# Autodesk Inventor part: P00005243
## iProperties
Shininess: 64.0
Length Units: 11269
Angle Units: 11279
Time Units: 11290
Mass Units: 11283
Length Display Precision: 3
Angle Display Precision: 2
Compacted: True
Part Number: P00005243
Document SubType Name: Modeling
Created: 2004-01
Material: Stahl (schweißbar)
Designer: Mittelmeyer
Manufacturer: Standard
Standards Organization: Custom
Density: 0.0
Volumn: 0.0
Area: 0.0
PropertySet Name: Model Information
Control State: 0
Master: False
Checked Out: False
Author: Mittelmeyer
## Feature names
1. Basis1
